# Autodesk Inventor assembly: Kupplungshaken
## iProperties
Shininess: 20.0
Angle Display Precision: 2
Document Length Units: 11269
Document Angle Units: 11279
Document Time Units: 11290
Document Mass Units: 11283
Document Length Units Precision: 3
Document Angle Units Precision: 2
Created: 2003-04
Part Number: Kupplungshaken
Document SubType Name: Baugruppe
Designer: Administrator
Density: 0.0
Volumn: 0.0
Area: 0.0
PropertySet Name: Model Information
Control State: 0
Master: False
Checked Out: False
Author: Administrator
